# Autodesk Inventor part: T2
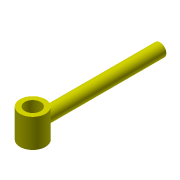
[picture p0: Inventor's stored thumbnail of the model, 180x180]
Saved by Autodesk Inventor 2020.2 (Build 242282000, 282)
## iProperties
Created: 2005-10
Part Number: T2
Document SubType Name: Modeling
Designer: F.Stasiak
Density: 1 g/cm^3
Material: Ogólny
Appearance: Żółty
Manager: www.cadconsulting.pl
Company: Fabian Stasiak CAD Consulting
Author: F.Stasiak
Subject: Zbiór ćwiczeń. Autodesk Inventor 2020. Kurs podstawowy
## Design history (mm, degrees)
sketch "Szkic1"
  geometry: L1 (0, 0)-(-20, 0); L2 (-20, 0)-(-20, -400); L3 (-20, -400)-(0, -400); L4 (0, -400)-(0, 0); C1 r 40 at (0, -400); C2 r 25 at (0, -400)
  constraints: 8 end point, 2 centre point, 2 coincident, 2 parallel, 1 horizontal, 1 perpendicular
  dimensions: "d0" = 20 distance of L2.end L3.end; "d1" = 400 distance of L3.end L1.start; "d2" = 80 diameter of C1; "d3" = 50 diameter of C2
revolve "Obrót1" stored, may be unused: angle "d4" = 90 deg
extrude "Wyciągnięcie proste1" join sketch "Szkic1" stored distance "d5" = 90; taper "d6" = 0 deg
extrude "Wyciągnięcie proste2" cut sketch "Szkic1" extent not by distance; stored distance "d7" = 120; taper "d8" = 0 deg
node "Bryła1"
node "Korpusy bryłowe"
node "Korpusy powierzchniowe"
